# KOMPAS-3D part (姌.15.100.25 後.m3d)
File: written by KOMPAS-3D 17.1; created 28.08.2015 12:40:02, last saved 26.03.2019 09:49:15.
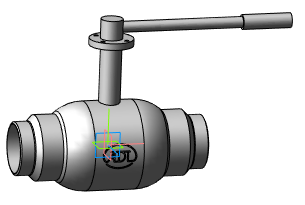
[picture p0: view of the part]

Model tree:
1. Операция без истории:4  (labels: Сталь 20  ГОСТ 1050-88)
